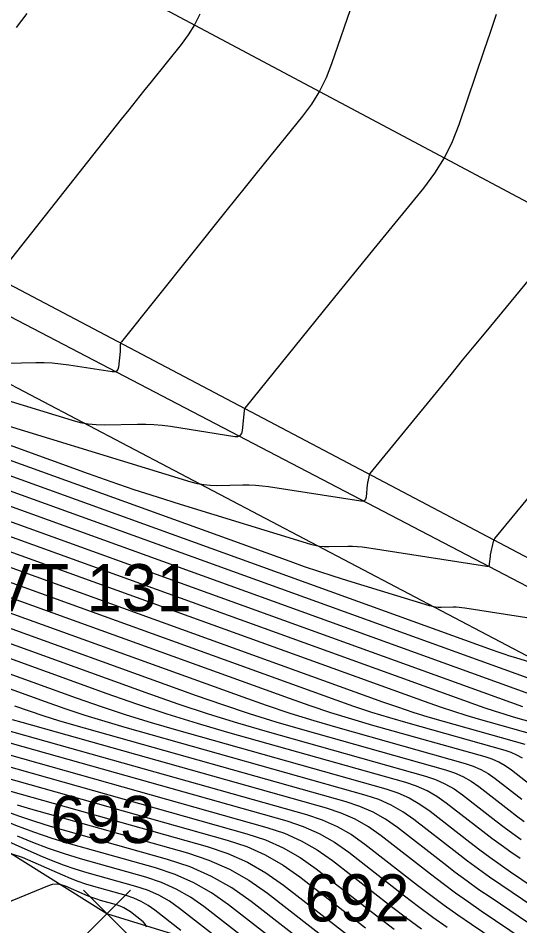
# Model space of a CAD drawing. Extents: x 1650836 to 1652450, y 332578 to 333908.
# Drawn here: x 1652080.03 to 1652101.34, y 332763.95 to 332802.49 of the extents above; entities that cross this region are included whole.
import ezdxf

# ---------------------------------------------------------------- set-up
doc = ezdxf.new("R2010")
doc.units = 0
for name, color, linetype in [('L_I', 7, 'Continuous'), ('L_TIC', 7, 'Continuous'), ('LELB', 7, 'Continuous'), ('LSOGCMA', 7, 'Continuous'), ('LSOGCMI', 7, 'Continuous'), ('PET', 7, 'Continuous'), ('PRC', 7, 'Continuous'), ('RGR', 7, 'Continuous'), ('S_C', 7, 'Continuous')]:
    doc.layers.add(name, color=color, linetype=linetype)

msp = doc.modelspace()

# ---------------------------------------------------------------- linework, layer by layer
at = {"layer": 'L_TIC'}
for points in [[(1652082.802, 332763.466), (1652084.802, 332765.466)], [(1652084.802, 332763.466), (1652082.802, 332765.466)]]:
    msp.add_lwpolyline(points, dxfattribs=at)
at = {"layer": 'LELB'}
for points in [[(1651844.759, 332915.941), (1651880.379, 332894.976), (1651917.082, 332874.787), (1651949.824, 332853.945), (1651967.074, 332844.342), (1652000.53, 332828.254), (1652035.357, 332809.776), (1652067.23, 332793.489), (1652106.029, 332773.108), (1652143.274, 332753.324), (1652172.167, 332734.049)], [(1652048.756, 332662.461), (1652082.555, 332678.298), (1652130.366, 332703.201), (1652148.083, 332715.406), (1652159.47, 332726.367), (1652148.02, 332734.227), (1652128.413, 332739.339), (1652116.951, 332747.33), (1652106.793, 332756.875), (1652094.604, 332761.138), (1652083.802, 332764.466), (1652074.482, 332770.284), (1652065.17, 332770.428), (1652062.989, 332774.387), (1652054.537, 332784.724), (1652034.993, 332796.475), (1652025.062, 332801.1), (1652009.772, 332808.074), (1651988.967, 332816.401), (1651980.006, 332832.954), (1651960.575, 332843.477), (1651932.852, 332862.75), (1651890.753, 332886.019), (1651847.527, 332911.35)]]:
    msp.add_lwpolyline(points, dxfattribs=at)
at = {"layer": 'LSOGCMA'}
for points in [[(1652087.742, 332802.657), (1652087.517, 332802.207), (1652087.254, 332801.779), (1652086.954, 332801.372), (1652085.679, 332799.784), (1652085.36, 332799.387), (1652085.043, 332798.989), (1652084.725, 332798.591), (1652084.408, 332798.193), (1652079.147, 332791.563)], [(1652103.234, 332772.208), (1652101.073, 332772.816), (1652100.668, 332772.934), (1652100.265, 332773.059), (1652099.865, 332773.192), (1652099.467, 332773.331), (1652077.425, 332781.287)], [(1652105.207, 332762.525), (1652100.525, 332765.691), (1652100.049, 332766.019), (1652099.579, 332766.354), (1652099.114, 332766.697), (1652098.655, 332767.048), (1652096.83, 332768.467), (1652096.362, 332768.797), (1652095.868, 332769.078), (1652095.349, 332769.309), (1652094.805, 332769.49), (1652084.572, 332772.372), (1652083.72, 332772.62), (1652082.873, 332772.883), (1652082.03, 332773.162), (1652081.193, 332773.456), (1652077.852, 332774.661)], [(1652094.602, 332761.343), (1652089.923, 332764.982), (1652089.102, 332765.56), (1652088.237, 332766.051), (1652087.329, 332766.455), (1652086.377, 332766.773), (1652081.409, 332768.172), (1652080.732, 332768.375), (1652080.062, 332768.603), (1652079.402, 332768.854)]]:
    msp.add_lwpolyline(points, dxfattribs=at)
at = {"layer": 'LSOGCMI'}
for points in [[(1652094.261, 332803.207), (1652093.344, 332800.551), (1652093.109, 332799.953), (1652092.824, 332799.382), (1652092.491, 332798.839), (1652092.108, 332798.323), (1652090.479, 332796.312), (1652090.072, 332795.81), (1652089.665, 332795.306), (1652089.26, 332794.802), (1652088.855, 332794.297), (1652084.413, 332788.75), (1652084.394, 332788.721), (1652084.38, 332788.691), (1652084.371, 332788.658), (1652084.368, 332788.624), (1652084.366, 332788.482), (1652084.365, 332788.447), (1652084.364, 332788.411), (1652084.361, 332788.376), (1652084.358, 332788.341), (1652084.29, 332787.675), (1652084.264, 332787.57), (1652084.211, 332787.501), (1652084.13, 332787.467), (1652084.022, 332787.468), (1652082.177, 332787.756), (1652081.828, 332787.802), (1652081.479, 332787.833), (1652081.128, 332787.849), (1652080.776, 332787.85), (1652078.926, 332787.811)], [(1652076.256, 332787.272), (1652082.321, 332785.415), (1652082.658, 332785.326), (1652082.999, 332785.265), (1652083.345, 332785.231), (1652083.694, 332785.225), (1652085.097, 332785.254), (1652085.448, 332785.254), (1652085.797, 332785.238), (1652086.145, 332785.207), (1652086.493, 332785.16), (1652089.239, 332784.732), (1652089.366, 332784.731), (1652089.46, 332784.771), (1652089.523, 332784.852), (1652089.553, 332784.975), (1652089.639, 332785.817), (1652089.64, 332785.826), (1652089.641, 332785.835), (1652089.643, 332785.844), (1652089.645, 332785.854), (1652089.653, 332785.89), (1652089.655, 332785.899), (1652089.658, 332785.908), (1652089.663, 332785.916), (1652089.668, 332785.923), (1652093.295, 332790.412), (1652093.788, 332791.022), (1652094.282, 332791.631), (1652094.778, 332792.239), (1652095.274, 332792.847), (1652097.26, 332795.276), (1652097.726, 332795.9), (1652098.13, 332796.558), (1652098.474, 332797.25), (1652098.756, 332797.976), (1652099.822, 332801.12), (1652100.085, 332801.892), (1652100.348, 332802.663)], [(1652079.954, 332802.098), (1652080.184, 332802.389), (1652080.414, 332802.681)], [(1652036.958, 332796.205), (1652059.028, 332789.196), (1652059.703, 332788.967), (1652060.367, 332788.711), (1652061.02, 332788.429), (1652061.662, 332788.121), (1652064.21, 332786.833), (1652064.85, 332786.518), (1652065.496, 332786.218), (1652066.149, 332785.931), (1652066.808, 332785.658), (1652071.714, 332783.691), (1652072.145, 332783.536), (1652072.583, 332783.414), (1652073.029, 332783.323), (1652073.483, 332783.265), (1652075.314, 332783.097), (1652075.769, 332783.041), (1652076.217, 332782.956), (1652076.659, 332782.843), (1652077.094, 332782.701), (1652103.425, 332773.197)], [(1652036.597, 332795.57), (1652058.137, 332788.73), (1652058.885, 332788.476), (1652059.621, 332788.192), (1652060.345, 332787.879), (1652061.057, 332787.537), (1652063.881, 332786.11), (1652064.591, 332785.761), (1652065.308, 332785.428), (1652066.031, 332785.11), (1652066.762, 332784.808), (1652070.826, 332783.178), (1652071.341, 332782.993), (1652071.865, 332782.846), (1652072.398, 332782.738), (1652072.941, 332782.669), (1652075.131, 332782.468), (1652075.674, 332782.401), (1652076.21, 332782.299), (1652076.739, 332782.164), (1652077.26, 332781.994), (1652101.446, 332773.264)], [(1652102.41, 332792.23), (1652099.885, 332789.17), (1652099.388, 332788.567), (1652098.893, 332787.963), (1652098.398, 332787.359), (1652097.904, 332786.754), (1652094.966, 332783.15), (1652094.956, 332783.136), (1652094.948, 332783.121), (1652094.941, 332783.105), (1652094.937, 332783.088), (1652094.877, 332782.809), (1652094.872, 332782.78), (1652094.867, 332782.75), (1652094.862, 332782.72), (1652094.859, 332782.69), (1652094.804, 332782.147), (1652094.782, 332782.06), (1652094.738, 332782.003), (1652094.672, 332781.975), (1652094.583, 332781.977), (1652090.663, 332782.588), (1652090.39, 332782.624), (1652090.116, 332782.649), (1652089.841, 332782.661), (1652089.565, 332782.661), (1652088.461, 332782.638), (1652088.187, 332782.643), (1652087.915, 332782.67), (1652087.647, 332782.718), (1652087.381, 332782.788), (1652077.296, 332785.876)], [(1652076.433, 332785.528), (1652083, 332783.158), (1652083.971, 332782.814), (1652084.947, 332782.482), (1652085.927, 332782.162), (1652086.911, 332781.854), (1652092.442, 332780.161), (1652092.635, 332780.11), (1652092.831, 332780.075), (1652093.029, 332780.056), (1652093.229, 332780.052), (1652094.033, 332780.069), (1652094.234, 332780.069), (1652094.434, 332780.06), (1652094.634, 332780.042), (1652094.833, 332780.015), (1652099.927, 332779.221), (1652099.978, 332779.22), (1652100.016, 332779.236), (1652100.041, 332779.269), (1652100.054, 332779.319), (1652100.085, 332779.631), (1652100.087, 332779.648), (1652100.09, 332779.665), (1652100.093, 332779.682), (1652100.096, 332779.699), (1652100.217, 332780.27), (1652100.226, 332780.302), (1652100.239, 332780.333), (1652100.255, 332780.362), (1652100.274, 332780.389), (1652102.68, 332783.313)], [(1652105.271, 332776.465), (1652099.003, 332777.443), (1652098.878, 332777.459), (1652098.753, 332777.47), (1652098.627, 332777.476), (1652098.501, 332777.476), (1652097.996, 332777.466), (1652097.871, 332777.468), (1652097.747, 332777.48), (1652097.624, 332777.502), (1652097.503, 332777.534), (1652094.032, 332778.597), (1652093.414, 332778.79), (1652092.8, 332778.991), (1652092.187, 332779.199), (1652091.577, 332779.415), (1652076.598, 332784.822)], [(1652076.763, 332784.115), (1652100.155, 332775.671), (1652100.403, 332775.584), (1652100.652, 332775.499), (1652100.902, 332775.417), (1652101.153, 332775.339), (1652102.563, 332774.907)], [(1652076.929, 332783.408), (1652105.405, 332773.13)], [(1652102.391, 332771.936), (1652099.579, 332772.728), (1652099.051, 332772.881), (1652098.527, 332773.044), (1652098.006, 332773.217), (1652097.487, 332773.399), (1652077.59, 332780.58)], [(1652077.756, 332779.874), (1652095.508, 332773.466), (1652096.146, 332773.242), (1652096.789, 332773.029), (1652097.434, 332772.829), (1652098.084, 332772.639), (1652101.548, 332771.664)], [(1652101.444, 332771.064), (1652101.21, 332771.197), (1652100.963, 332771.306), (1652100.706, 332771.392), (1652096.589, 332772.551), (1652095.818, 332772.776), (1652095.05, 332773.015), (1652094.287, 332773.267), (1652093.529, 332773.533), (1652077.921, 332779.167)], [(1652101.978, 332769.779), (1652100.975, 332770.559), (1652100.718, 332770.74), (1652100.446, 332770.894), (1652100.161, 332771.021), (1652099.863, 332771.121), (1652095.095, 332772.463), (1652094.201, 332772.723), (1652093.312, 332773), (1652092.428, 332773.292), (1652091.549, 332773.6), (1652078.086, 332778.46)], [(1652078.252, 332777.753), (1652089.57, 332773.668), (1652090.569, 332773.317), (1652091.573, 332772.985), (1652092.584, 332772.671), (1652093.6, 332772.375), (1652099.02, 332770.849), (1652099.359, 332770.736), (1652099.683, 332770.591), (1652099.992, 332770.416), (1652100.284, 332770.21), (1652101.424, 332769.324)], [(1652078.417, 332777.046), (1652087.591, 332773.735), (1652088.71, 332773.342), (1652089.835, 332772.97), (1652090.967, 332772.618), (1652092.105, 332772.287), (1652098.177, 332770.577), (1652098.557, 332770.45), (1652098.92, 332770.289), (1652099.266, 332770.093), (1652099.594, 332769.862), (1652100.87, 332768.869), (1652101.191, 332768.623), (1652101.516, 332768.383)], [(1652078.583, 332776.339), (1652085.611, 332773.802), (1652086.85, 332773.367), (1652088.097, 332772.955), (1652089.35, 332772.566), (1652090.611, 332772.198), (1652097.334, 332770.305), (1652097.755, 332770.165), (1652098.157, 332769.986), (1652098.54, 332769.769), (1652098.903, 332769.513), (1652100.316, 332768.414), (1652100.672, 332768.142), (1652101.032, 332767.876), (1652101.396, 332767.616)], [(1652101.352, 332766.805), (1652100.947, 332767.084), (1652100.548, 332767.369), (1652100.153, 332767.66), (1652099.763, 332767.959), (1652098.212, 332769.165), (1652097.814, 332769.445), (1652097.394, 332769.683), (1652096.953, 332769.88), (1652096.491, 332770.034), (1652088.94, 332772.16), (1652087.645, 332772.537), (1652086.357, 332772.937), (1652085.077, 332773.361), (1652083.804, 332773.807), (1652078.728, 332775.64)], [(1652078.29, 332775.15), (1652082.498, 332773.631), (1652083.554, 332773.261), (1652084.615, 332772.91), (1652085.682, 332772.578), (1652086.756, 332772.266), (1652095.648, 332769.762), (1652096.151, 332769.594), (1652096.631, 332769.381), (1652097.088, 332769.121), (1652097.521, 332768.816), (1652099.209, 332767.503), (1652099.633, 332767.179), (1652100.063, 332766.861), (1652100.498, 332766.551), (1652100.938, 332766.248), (1652105.269, 332763.32)], [(1652105.145, 332761.73), (1652100.112, 332765.134), (1652099.6, 332765.486), (1652099.094, 332765.847), (1652098.595, 332766.216), (1652098.101, 332766.593), (1652096.14, 332768.119), (1652095.636, 332768.474), (1652095.105, 332768.775), (1652094.547, 332769.024), (1652093.963, 332769.219), (1652082.388, 332772.477), (1652081.757, 332772.661), (1652081.13, 332772.856), (1652080.507, 332773.062), (1652079.887, 332773.28)], [(1652076.295, 332772.666), (1652091.434, 332768.403), (1652092.141, 332768.168), (1652092.816, 332767.867), (1652093.458, 332767.502), (1652094.067, 332767.073), (1652096.44, 332765.228), (1652097.037, 332764.771), (1652097.641, 332764.325), (1652098.253, 332763.889)], [(1652078.02, 332772.689), (1652092.277, 332768.675), (1652092.943, 332768.453), (1652093.579, 332768.17), (1652094.184, 332767.826), (1652094.758, 332767.422), (1652096.994, 332765.683), (1652097.556, 332765.253), (1652098.126, 332764.832), (1652098.702, 332764.421), (1652099.285, 332764.02), (1652105.022, 332760.14)], [(1652105.083, 332760.935), (1652099.698, 332764.577), (1652099.151, 332764.954), (1652098.61, 332765.34), (1652098.076, 332765.734), (1652097.548, 332766.138), (1652095.449, 332767.77), (1652094.91, 332768.15), (1652094.342, 332768.473), (1652093.745, 332768.738), (1652093.12, 332768.947), (1652080.204, 332772.583), (1652079.795, 332772.702)], [(1652077.148, 332771.917), (1652090.591, 332768.132), (1652091.339, 332767.882), (1652092.053, 332767.565), (1652092.732, 332767.179), (1652093.376, 332766.725), (1652095.886, 332764.773), (1652096.518, 332764.29), (1652097.157, 332763.818)], [(1652078, 332771.168), (1652089.748, 332767.86), (1652090.537, 332767.597), (1652091.29, 332767.262), (1652092.006, 332766.855), (1652092.686, 332766.376), (1652095.333, 332764.318), (1652095.999, 332763.808)], [(1652092.838, 332761.829), (1652088.962, 332764.844), (1652088.244, 332765.349), (1652087.489, 332765.778), (1652086.695, 332766.131), (1652085.863, 332766.409), (1652082.262, 332767.423), (1652081.474, 332767.66), (1652080.696, 332767.924), (1652079.928, 332768.216), (1652079.169, 332768.535), (1652075.443, 332770.181), (1652075.041, 332770.331), (1652074.631, 332770.431), (1652074.211, 332770.482), (1652073.783, 332770.482), (1652072.05, 332770.384), (1652071.624, 332770.337), (1652071.21, 332770.244), (1652070.809, 332770.105), (1652070.422, 332769.921), (1652068.874, 332769.082)], [(1652078.852, 332770.419), (1652088.905, 332767.588), (1652089.735, 332767.312), (1652090.526, 332766.959), (1652091.28, 332766.531), (1652091.995, 332766.028), (1652094.779, 332763.862)], [(1652079.705, 332769.67), (1652088.062, 332767.317), (1652088.933, 332767.026), (1652089.763, 332766.656), (1652090.554, 332766.207), (1652091.304, 332765.679), (1652094.583, 332763.129)], [(1652079.99, 332769.091), (1652080.557, 332768.921), (1652087.22, 332767.045), (1652088.131, 332766.741), (1652089, 332766.354), (1652089.828, 332765.884), (1652090.613, 332765.331), (1652094.593, 332762.236)], [(1652088.545, 332763.396), (1652086.88, 332764.691), (1652086.452, 332764.992), (1652086.001, 332765.248), (1652085.528, 332765.459), (1652085.031, 332765.625), (1652082.965, 332766.207), (1652082.454, 332766.36), (1652081.95, 332766.531), (1652081.452, 332766.72), (1652080.961, 332766.927), (1652077.808, 332768.32)], [(1652090.547, 332762.725), (1652087.921, 332764.767), (1652087.348, 332765.17), (1652086.745, 332765.513), (1652086.112, 332765.795), (1652085.447, 332766.017), (1652082.682, 332766.795), (1652081.999, 332767.001), (1652081.324, 332767.23), (1652080.658, 332767.483), (1652080, 332767.76)], [(1652086.941, 332763.758), (1652085.839, 332764.615), (1652085.556, 332764.814), (1652085.257, 332764.984), (1652084.944, 332765.123), (1652084.616, 332765.233), (1652083.248, 332765.618), (1652082.91, 332765.719), (1652082.576, 332765.833), (1652082.247, 332765.958), (1652081.922, 332766.095), (1652080.213, 332766.849), (1652079.82, 332766.981), (1652079.426, 332767.028), (1652079.031, 332766.991), (1652078.635, 332766.87), (1652075.74, 332765.682), (1652075.318, 332765.502), (1652074.901, 332765.31), (1652074.489, 332765.108), (1652074.083, 332764.895), (1652072.469, 332764.019), (1652072.12, 332763.771)], [(1652085.481, 332763.9), (1652085.44, 332764.012), (1652085.337, 332764.12), (1652084.798, 332764.539), (1652084.659, 332764.636), (1652084.514, 332764.719), (1652084.36, 332764.787), (1652084.2, 332764.841), (1652083.531, 332765.029), (1652083.366, 332765.079), (1652083.203, 332765.134), (1652083.042, 332765.195), (1652082.883, 332765.262), (1652082.047, 332765.631), (1652081.855, 332765.695), (1652081.663, 332765.719), (1652081.469, 332765.701), (1652081.276, 332765.641), (1652075.588, 332763.306)]]:
    msp.add_lwpolyline(points, dxfattribs=at)
at = {"layer": 'PET'}
msp.add_lwpolyline([(1651764.546, 332972.615), (1651784.506, 332958.597), (1651809.702, 332941.927), (1651846.26, 332918.158), (1651881.765, 332897.162), (1651918.116, 332876.642), (1651951.432, 332858.415), (1651975.296, 332845.48), (1652002.223, 332831.337), (1652037.173, 332813.417), (1652069.296, 332796.636), (1652107.428, 332776.545), (1652145.079, 332756.921), (1652175.234, 332740.226), (1652190.754, 332731.861), (1652206.573, 332723.523), (1652239.422, 332706.921), (1652282.404, 332684.366), (1652332.494, 332658.525), (1652365.542, 332641.171), (1652388.914, 332629.021)], dxfattribs=at)
at = {"layer": 'PRC'}
msp.add_lwpolyline([(1651773.612, 332982.822), (1651792.672, 332969.525), (1651816.542, 332953.47), (1651853.779, 332929.89), (1651888.829, 332909.027), (1651925.09, 332888.189), (1651957.726, 332870.48), (1651982.519, 332857.297), (1652019.654, 332837.681), (1652042.767, 332825.192), (1652076.048, 332808.311), (1652114.48, 332787.851), (1652150.944, 332769.103), (1652185.791, 332750.516), (1652225.777, 332729.89), (1652246.28, 332718.635), (1652288.707, 332696.529), (1652339.002, 332669.86), (1652372.556, 332652.699), (1652395.364, 332640.33)], dxfattribs=at)
at = {"layer": 'RGR'}
msp.add_lwpolyline([(1651963.926, 332842.71), (1651967.074, 332844.342), (1651975.028, 332844.451), (1652001.752, 332830.477), (1652036.76, 332812.304), (1652068.698, 332795.548), (1652107.135, 332775.504), (1652144.421, 332755.8), (1652165.98, 332744.268), (1652170.761, 332738.792), (1652172.167, 332734.049)], dxfattribs=at)

# ---------------------------------------------------------------- texts
at = {"layer": 'L_I'}
for s, p in [('693', (1652081.393, 332767.466)), ('692', (1652092.195, 332764.138))]:
    msp.add_text(s, height=2, dxfattribs=at).set_placement(p)
at = {"layer": 'S_C'}
msp.add_text('BRIDGE 15 VT 131', height=2, dxfattribs=at).set_placement((1652064.061, 332777.31))

doc.saveas('drawing.dxf')
